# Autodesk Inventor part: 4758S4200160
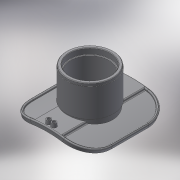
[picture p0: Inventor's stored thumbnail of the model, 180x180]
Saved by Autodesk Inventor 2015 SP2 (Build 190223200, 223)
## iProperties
Created: 2017-08
Part Number: 4758S4200160
Material: Generic
Description: PLASSON WASTEWATER SADDLE 200X160 SPIGOT INLET
Document SubType Name: Modeling
Designer: Кирилл
Density: 1 g/cm^3
Appearance: Default
Author: Кирилл
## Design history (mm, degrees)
derived "4758S4.ipt"
feature "Solid1::4758S4.ipt"
feature "Solid2::4758S4.ipt"
feature "Solid3::4758S4.ipt"
tag "TaggingFeature1"
body "Solid1"
other parameters: "d1" = 208, "d4" = 0, "d5" = 62.4, "d6" = 6.4, "d7" = 30 deg, "d8" = 15 deg, "d10" = 0, "d38" = 1, "d40" = 126, "d41" = 15, "d42" = 130.5, "d43" = 17.6, "d44" = 8.8, "d46" = 5 deg, "d47" = 4, "d49" = 4, "d51" = 14, "d52" = 0, "d53" = 3, "d54" = 0, "d75" = 0, "d77" = 0, "d78" = 1.6, "d82" = 125, "d84" = 156.8, "d85" = 128, "d86" = 136, "d87" = 18.75, "d88" = 152, "d89" = 18.75, "d90" = 9.375, "d91" = 1.6, "B_" = 208, "H_" = 125
